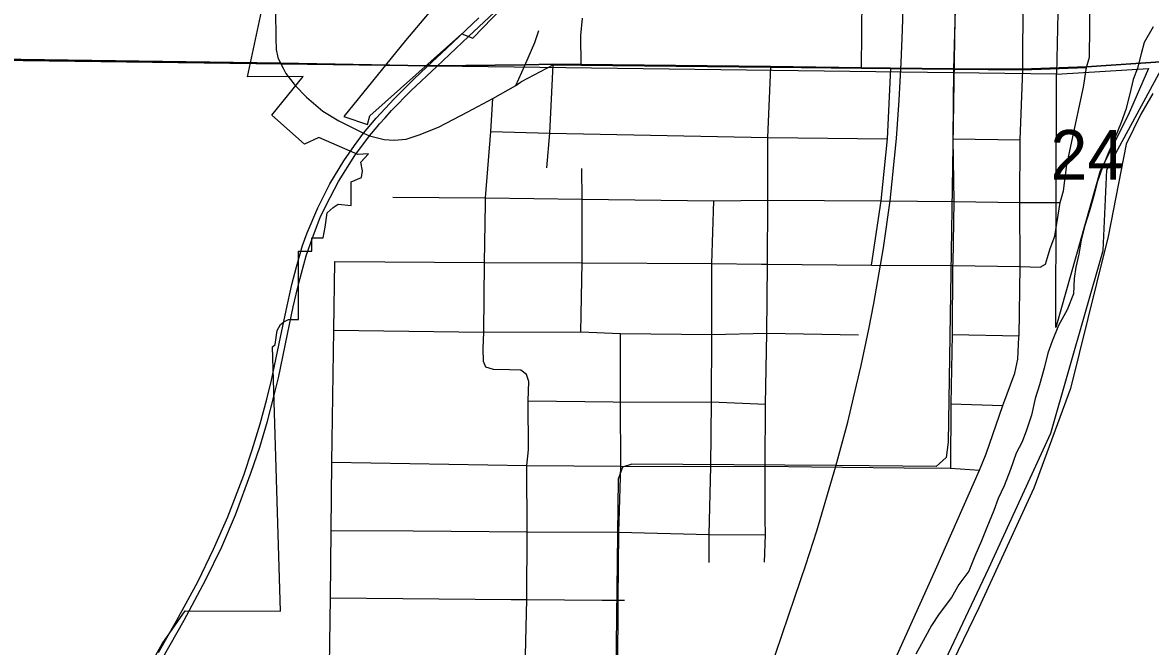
# Model space of a CAD drawing. Extents: x 0 to 34, y 0 to 22.
# Drawn here: x 7.567 to 8.519, y 18.613 to 19.139 of the extents above; entities that cross this region are included whole.
import ezdxf

# ---------------------------------------------------------------- set-up
doc = ezdxf.new("R2010")
doc.units = 0
for name, color, linetype in [('Default', 7, 'Continuous'), ('GM_X_City_Street', 7, 'Continuous'), ('GM_X_Corporation', 7, 'Continuous'), ('GM_X_County_Road', 7, 'Continuous'), ('GM_X_Major_River', 7, 'Continuous'), ('GM_X_Rail_Line', 7, 'Continuous'), ('GM_X_Section', 7, 'Continuous'), ('GM_X_Section_Text', 7, 'Continuous'), ('GM_X_State_Route', 7, 'Continuous'), ('SH_Cut_Line', 7, 'Continuous')]:
    doc.layers.add(name, color=color, linetype=linetype)

msp = doc.modelspace()

# ---------------------------------------------------------------- linework, layer by layer
at = {"layer": 'Default'}
for p, q in [((7.78452, 19.10445), (7.43931, 19.10971)), ((7.43931, 19.10971), (7.78452, 19.10445)), ((7.90755, 19.10221), (7.78452, 19.10445)), ((7.78452, 19.10445), (7.90755, 19.10221)), ((8.01461, 19.10384), (7.99063, 19.10309)), ((7.99063, 19.10309), (8.01461, 19.10384)), ((8.03819, 19.10356), (8.01461, 19.10384)), ((8.01461, 19.10384), (8.03819, 19.10356)), ((8.19825, 19.10168), (8.03819, 19.10356)), ((8.03819, 19.10356), (8.19825, 19.10168)), ((8.53181, 19.10605), (8.46497, 19.10144)), ((8.46497, 19.10144), (8.53181, 19.10605)), ((8.48217, 19.01472), (8.53181, 19.10605)), ((7.90825, 19.10222), (7.90755, 19.10221)), ((7.90755, 19.10221), (7.90825, 19.10222)), ((7.91626, 19.1023), (7.90825, 19.10222)), ((7.90825, 19.10222), (7.91626, 19.1023)), ((7.99063, 19.10309), (7.91626, 19.1023)), ((7.91626, 19.1023), (7.99063, 19.10309)), ((8.27493, 19.10078), (8.19825, 19.10168)), ((8.19825, 19.10168), (8.27493, 19.10078)), ((8.29966, 19.1005), (8.27493, 19.10078)), ((8.27493, 19.10078), (8.29966, 19.1005)), ((8.35257, 19.09993), (8.29966, 19.1005)), ((8.29966, 19.1005), (8.35257, 19.09993)), ((8.41097, 19.09961), (8.35257, 19.09993)), ((8.35257, 19.09993), (8.41097, 19.09961)), ((8.46497, 19.10144), (8.41097, 19.09961)), ((8.41097, 19.09961), (8.46497, 19.10144)), ((8.47905, 18.9465), (8.48217, 19.01472)), ((8.43501, 18.79263), (8.47905, 18.9465)), ((8.38262, 18.67861), (8.43501, 18.79263)), ((8.32753, 18.56228), (8.38262, 18.67861))]:
    msp.add_line(p, q, dxfattribs=at)
at = {"layer": 'GM_X_City_Street'}
for p, q in [((8.27513, 19.10024), (8.27561, 19.16337)), ((8.46748, 19.10967), (8.46826, 19.16076)), ((8.03812, 19.12792), (8.03943, 19.14251)), ((7.99919, 19.122), (8.00248, 19.13217)), ((8.03838, 19.10302), (8.03812, 19.12792)), ((7.99082, 19.10255), (7.99919, 19.122)), ((8.01179, 19.04554), (8.0148, 19.1033)), ((8.46516, 19.10089), (8.46748, 19.10967)), ((7.98324, 19.08564), (7.99082, 19.10255)), ((8.29698, 19.04065), (8.29986, 19.09996)), ((8.41116, 19.09907), (8.46516, 19.10089)), ((8.46253, 19.08438), (8.46516, 19.10089)), ((8.44845, 19.01895), (8.46253, 19.08438)), ((7.962, 19.04684), (7.96388, 19.07476)), ((7.95757, 18.99105), (7.962, 19.04684)), ((7.962, 19.04684), (8.01179, 19.04554)), ((8.00945, 19.01634), (8.01179, 19.04554)), ((8.01179, 19.04554), (8.19584, 19.04189)), ((8.19584, 19.04189), (8.29698, 19.04065)), ((8.29171, 18.98849), (8.29698, 19.04065)), ((8.35226, 19.04085), (8.40909, 19.0398)), ((8.44558, 18.99679), (8.44845, 19.01895)), ((8.03917, 18.99001), (8.03891, 19.01582)), ((7.87936, 18.99158), (7.95757, 18.99105)), ((7.9575, 18.9861), (7.95757, 18.99105)), ((7.95757, 18.99105), (8.03917, 18.99001)), ((8.03916, 18.93611), (8.03917, 18.99001)), ((8.03917, 18.99001), (8.15048, 18.98845)), ((8.15048, 18.98845), (8.19584, 18.98897)), ((8.19584, 18.98897), (8.29171, 18.98849)), ((8.44271, 18.98714), (8.44558, 18.99679)), ((7.95679, 18.93656), (7.9575, 18.9861)), ((8.14866, 18.93547), (8.15048, 18.98845)), ((8.28343, 18.93432), (8.29171, 18.98849)), ((8.29171, 18.98849), (8.35304, 18.98793)), ((8.35304, 18.98793), (8.40882, 18.98714)), ((8.40882, 18.98714), (8.44271, 18.98714)), ((8.43828, 18.95873), (8.44271, 18.98714)), ((8.43437, 18.9483), (8.43828, 18.95873)), ((8.43203, 18.94074), (8.43437, 18.9483)), ((7.82946, 18.87925), (7.83051, 18.93726)), ((7.83051, 18.93726), (7.95679, 18.93656)), ((7.95627, 18.87765), (7.95679, 18.93656)), ((7.95679, 18.93656), (8.03916, 18.93611)), ((8.03812, 18.87792), (8.03916, 18.93611)), ((8.03916, 18.93611), (8.14866, 18.93547)), ((8.14866, 18.87583), (8.14866, 18.93547)), ((8.14866, 18.93547), (8.19059, 18.93511)), ((8.19059, 18.93511), (8.19558, 18.93507)), ((8.19558, 18.93507), (8.28343, 18.93432)), ((8.28343, 18.93432), (8.352, 18.9339)), ((8.352, 18.9339), (8.40915, 18.93317)), ((8.40915, 18.93317), (8.42603, 18.9324)), ((8.42603, 18.9324), (8.43046, 18.93501)), ((8.43046, 18.93501), (8.43203, 18.94074)), ((7.82788, 18.76807), (7.82946, 18.87925)), ((7.82946, 18.87925), (7.95627, 18.87765)), ((7.95575, 18.86384), (7.95627, 18.87765)), ((7.95627, 18.87765), (8.03812, 18.87792)), ((8.03812, 18.87792), (8.07149, 18.87661)), ((8.07149, 18.87661), (8.14866, 18.87583)), ((8.07149, 18.81874), (8.07149, 18.87661)), ((8.1484, 18.819), (8.14866, 18.87583)), ((8.14866, 18.87583), (8.19506, 18.87687)), ((8.19506, 18.87687), (8.27248, 18.87557)), ((8.35147, 18.87583), (8.40804, 18.87453)), ((7.95601, 18.85289), (7.95575, 18.86384)), ((7.95783, 18.8482), (7.95601, 18.85289)), ((7.96435, 18.84611), (7.95783, 18.8482)), ((7.97791, 18.84585), (7.96435, 18.84611)), ((7.98755, 18.84559), (7.97791, 18.84585)), ((7.99224, 18.84194), (7.98755, 18.84559)), ((7.99407, 18.83621), (7.99224, 18.84194)), ((7.99355, 18.81978), (7.99407, 18.83621)), ((7.99355, 18.81978), (8.06534, 18.81882)), ((7.99381, 18.77833), (7.99355, 18.81978)), ((8.06534, 18.81882), (8.07149, 18.81874)), ((8.07149, 18.81874), (8.1484, 18.819)), ((8.07186, 18.76456), (8.07149, 18.81874)), ((8.14787, 18.76425), (8.1484, 18.819)), ((8.1484, 18.819), (8.19402, 18.81691)), ((8.35043, 18.81717), (8.39449, 18.81587)), ((7.9925, 18.7653), (7.99381, 18.77833)), ((7.82723, 18.71043), (7.82788, 18.76807)), ((7.82788, 18.76807), (7.9925, 18.7653)), ((7.99277, 18.70939), (7.9925, 18.7653)), ((7.9925, 18.7653), (8.07186, 18.76456)), ((8.14631, 18.7069), (8.14787, 18.76425)), ((8.19376, 18.7202), (8.19376, 18.76452)), ((8.33746, 18.67727), (8.37467, 18.76139)), ((8.19402, 18.70664), (8.19376, 18.7202)), ((7.82658, 18.6535), (7.82723, 18.71043)), ((7.82723, 18.71043), (7.89662, 18.70999)), ((7.89662, 18.70999), (7.99277, 18.70939)), ((7.99251, 18.65216), (7.99277, 18.70939)), ((7.99277, 18.70939), (8.07011, 18.70895)), ((8.07011, 18.70895), (8.14631, 18.7069)), ((8.14631, 18.68344), (8.14631, 18.7069)), ((8.14631, 18.7069), (8.19402, 18.70664)), ((8.19323, 18.6837), (8.19402, 18.70664)), ((8.28799, 18.56768), (8.33746, 18.67727)), ((7.82592, 18.59663), (7.82658, 18.6535)), ((7.82658, 18.6535), (7.97916, 18.65227)), ((7.97916, 18.65227), (7.99251, 18.65216)), ((7.99095, 18.5935), (7.99251, 18.65216)), ((7.99251, 18.65216), (8.05601, 18.65165)), ((8.05601, 18.65165), (8.06948, 18.65154)), ((8.06948, 18.65154), (8.07508, 18.6515))]:
    msp.add_line(p, q, dxfattribs=at)
at = {"layer": 'GM_X_Corporation'}
for p, q in [((7.75651, 19.09318), (7.7916, 19.25476)), ((7.94699, 19.12564), (7.99145, 19.17211)), ((7.9193, 19.15858), (7.89001, 19.12359)), ((7.89001, 19.12359), (7.83796, 19.0597)), ((7.85995, 19.06011), (7.93758, 19.1293)), ((7.93758, 19.1293), (7.94699, 19.12564)), ((7.80375, 19.09336), (7.75651, 19.09318)), ((7.77714, 19.06079), (7.80375, 19.09336)), ((8.521, 19.07889), (8.51095, 19.06147)), ((7.80485, 19.03639), (7.77714, 19.06079)), ((7.83796, 19.0597), (7.85805, 19.05291)), ((7.85805, 19.05291), (7.85995, 19.06011)), ((8.51095, 19.06147), (8.49851, 19.0364)), ((7.81687, 19.04199), (7.80485, 19.03639)), ((7.84992, 19.02753), (7.81687, 19.04199)), ((7.85868, 19.02822), (7.84992, 19.02753)), ((7.85241, 19.02103), (7.85868, 19.02822)), ((8.49851, 19.0364), (8.48326, 18.95844)), ((7.85385, 19.01373), (7.85241, 19.02103)), ((7.84407, 19.00448), (7.85284, 19.00801)), ((7.85284, 19.00801), (7.85385, 19.01373)), ((7.84406, 18.98462), (7.84407, 19.00448)), ((7.82386, 18.97824), (7.82891, 18.98295)), ((7.82891, 18.98295), (7.83329, 18.98564)), ((7.83329, 18.98564), (7.84406, 18.98462)), ((7.82217, 18.96613), (7.82386, 18.97824)), ((7.82049, 18.95723), (7.82217, 18.96613)), ((7.81102, 18.94588), (7.81102, 18.95724)), ((7.81102, 18.95724), (7.82049, 18.95723)), ((8.48326, 18.95844), (8.47357, 18.91863)), ((7.79962, 18.88848), (7.79965, 18.94589)), ((7.79965, 18.94589), (7.81102, 18.94588)), ((8.47357, 18.91863), (8.45146, 18.83021)), ((7.78437, 18.88417), (7.78732, 18.88645)), ((7.78732, 18.88645), (7.79122, 18.88849)), ((7.79122, 18.88849), (7.79962, 18.88848)), ((7.77996, 18.86729), (7.78174, 18.87903)), ((7.78174, 18.87903), (7.78437, 18.88417)), ((7.77778, 18.8652), (7.77996, 18.86729)), ((7.78438, 18.6423), (7.77778, 18.8652)), ((8.45146, 18.83021), (8.42049, 18.74604)), ((8.42049, 18.74604), (8.37415, 18.64504)), ((7.68445, 18.61475), (7.70398, 18.6427)), ((7.70398, 18.6427), (7.78438, 18.6423)), ((8.37415, 18.64504), (8.34608, 18.58755)), ((7.64793, 18.54939), (7.68445, 18.61475))]:
    msp.add_line(p, q, dxfattribs=at)
at = {"layer": 'GM_X_County_Road'}
for p, q in [((8.3546, 19.16285), (8.35277, 19.09939)), ((8.41116, 19.09907), (8.41169, 19.16233)), ((7.78025, 19.14883), (7.78044, 19.12569)), ((7.78044, 19.12569), (7.78083, 19.11616)), ((7.78083, 19.11616), (7.78219, 19.10936)), ((7.78219, 19.10936), (7.78471, 19.10391)), ((7.78471, 19.10391), (7.78662, 19.10028)), ((7.98803, 19.08903), (8.0148, 19.1033)), ((8.0148, 19.1033), (8.03531, 19.10306)), ((7.78662, 19.10028), (7.789, 19.09575)), ((7.789, 19.09575), (7.79686, 19.0857)), ((8.03531, 19.10306), (8.03838, 19.10302)), ((8.03838, 19.10302), (8.19844, 19.10114)), ((8.19584, 19.04189), (8.19844, 19.10114)), ((8.19844, 19.10114), (8.27513, 19.10024)), ((8.27513, 19.10024), (8.29986, 19.09996)), ((8.29986, 19.09996), (8.35277, 19.09939)), ((8.35277, 19.09939), (8.35226, 19.04085)), ((8.35277, 19.09939), (8.41116, 19.09907)), ((8.40909, 19.0398), (8.41116, 19.09907)), ((7.79686, 19.0857), (7.80645, 19.07604)), ((7.96388, 19.07476), (7.98324, 19.08564)), ((7.98324, 19.08564), (7.98713, 19.08855)), ((7.98713, 19.08855), (7.98803, 19.08903)), ((7.80645, 19.07604), (7.82035, 19.06408)), ((7.94261, 19.06347), (7.96388, 19.07476)), ((7.82035, 19.06408), (7.83369, 19.05595)), ((7.83369, 19.05595), (7.85471, 19.04542)), ((7.91791, 19.05064), (7.94261, 19.06347)), ((7.90154, 19.04417), (7.91791, 19.05064)), ((7.85471, 19.04542), (7.85969, 19.04327)), ((7.85969, 19.04327), (7.87202, 19.04033)), ((7.87202, 19.04033), (7.88058, 19.03955)), ((7.88058, 19.03955), (7.89069, 19.04053)), ((7.89069, 19.04053), (7.90154, 19.04417)), ((8.19584, 18.98897), (8.19584, 19.04189)), ((8.35226, 19.04085), (8.35304, 18.98793)), ((8.40882, 18.98714), (8.40909, 19.0398)), ((8.19558, 18.93507), (8.19584, 18.98897)), ((8.35304, 18.98793), (8.35204, 18.93594)), ((8.40915, 18.93317), (8.40882, 18.98714)), ((8.19506, 18.87687), (8.19558, 18.93507)), ((8.352, 18.9339), (8.35147, 18.87583)), ((8.35204, 18.93594), (8.352, 18.9339)), ((8.40804, 18.87453), (8.40915, 18.93317)), ((8.19402, 18.81691), (8.19506, 18.87687)), ((8.35147, 18.87583), (8.35043, 18.81717)), ((8.407, 18.85497), (8.40799, 18.87355)), ((8.40799, 18.87355), (8.40804, 18.87453)), ((8.40465, 18.84324), (8.407, 18.85497)), ((8.39449, 18.81587), (8.40465, 18.84324)), ((8.19376, 18.76452), (8.19402, 18.81691)), ((8.35043, 18.81717), (8.35017, 18.76295)), ((8.38041, 18.7752), (8.39449, 18.81587)), ((8.37467, 18.76139), (8.38041, 18.7752)), ((8.07011, 18.70895), (8.07186, 18.76456)), ((8.07186, 18.76456), (8.14787, 18.76425)), ((8.14787, 18.76425), (8.19376, 18.76452)), ((8.19376, 18.76452), (8.23286, 18.76412)), ((8.23286, 18.76412), (8.31107, 18.76334)), ((8.31107, 18.76334), (8.35017, 18.76295)), ((8.35017, 18.76295), (8.37467, 18.76139)), ((8.06948, 18.65154), (8.07011, 18.70895)), ((8.06944, 18.59273), (8.06948, 18.65154))]:
    msp.add_line(p, q, dxfattribs=at)
at = {"layer": 'GM_X_Major_River'}
for p, q in [((8.52143, 19.13512), (8.51372, 19.12208)), ((8.51372, 19.12208), (8.51125, 19.11255)), ((8.51125, 19.11255), (8.50808, 19.10035)), ((8.50808, 19.10035), (8.50447, 19.09079)), ((8.50447, 19.09079), (8.50167, 19.0786)), ((8.50167, 19.0786), (8.49813, 19.06563)), ((8.49813, 19.06563), (8.49418, 19.05456)), ((8.49418, 19.05456), (8.48876, 19.0408)), ((8.48876, 19.0408), (8.48294, 19.02778)), ((8.48294, 19.02778), (8.47824, 19.01594)), ((8.47824, 19.01594), (8.47393, 19.00409)), ((8.47393, 19.00409), (8.47147, 18.9938)), ((8.47147, 18.9938), (8.46756, 18.98007)), ((8.46756, 18.98007), (8.46327, 18.96671)), ((8.46327, 18.96671), (8.46046, 18.95527)), ((8.46046, 18.95527), (8.45841, 18.94347)), ((8.45841, 18.94347), (8.45597, 18.93243)), ((8.45597, 18.93243), (8.45464, 18.92291)), ((8.45464, 18.92291), (8.45413, 18.91)), ((8.45413, 18.91), (8.4487, 18.89662)), ((8.4487, 18.89662), (8.44138, 18.8832)), ((8.44138, 18.8832), (8.43595, 18.8702)), ((8.43595, 18.8702), (8.43235, 18.85989)), ((8.43235, 18.85989), (8.42919, 18.84731)), ((8.42919, 18.84731), (8.42529, 18.83319)), ((8.42529, 18.83319), (8.42172, 18.82174)), ((8.42172, 18.82174), (8.41858, 18.80764)), ((8.41858, 18.80764), (8.41427, 18.79504)), ((8.41427, 18.79504), (8.41067, 18.78511)), ((8.41067, 18.78511), (8.40555, 18.77553)), ((8.40555, 18.77553), (8.40089, 18.76178)), ((8.40089, 18.76178), (8.39547, 18.74801)), ((8.39547, 18.74801), (8.39037, 18.73729)), ((8.39037, 18.73729), (8.38677, 18.72736)), ((8.38677, 18.72736), (8.38098, 18.71283)), ((8.38098, 18.71283), (8.37627, 18.70174)), ((8.37627, 18.70174), (8.37083, 18.68873)), ((8.37083, 18.68873), (8.36577, 18.67611)), ((8.36577, 18.67611), (8.35727, 18.66495)), ((8.35727, 18.66495), (8.35104, 18.65383)), ((8.35104, 18.65383), (8.34069, 18.63997)), ((8.34069, 18.63997), (8.33405, 18.63036)), ((8.33405, 18.63036), (8.32894, 18.62039)), ((8.32894, 18.62039), (8.32087, 18.6062))]:
    msp.add_line(p, q, dxfattribs=at)
at = {"layer": 'GM_X_Rail_Line'}
for p, q in [((8.35732, 19.35599), (8.34834, 18.78484)), ((8.30959, 19.13274), (8.31068, 19.16341)), ((8.3086, 19.10474), (8.30959, 19.13274)), ((8.30692, 19.07337), (8.3086, 19.10474)), ((8.30455, 19.04102), (8.30692, 19.07337)), ((8.2992, 18.98848), (8.30455, 19.04102)), ((8.29356, 18.9487), (8.2992, 18.98848)), ((8.2901, 18.92763), (8.29356, 18.9487)), ((8.28555, 18.902), (8.2901, 18.92763)), ((8.2812, 18.88013), (8.28555, 18.902)), ((8.27476, 18.84956), (8.2812, 18.88013)), ((8.26833, 18.82225), (8.27476, 18.84956)), ((8.26339, 18.80177), (8.26833, 18.82225)), ((8.25349, 18.76454), (8.26339, 18.80177)), ((8.34834, 18.78484), (8.34661, 18.77195)), ((8.34661, 18.77195), (8.33813, 18.76448)), ((8.07319, 18.76378), (8.0696, 18.75357)), ((8.08121, 18.76631), (8.07319, 18.76378)), ((8.2533, 18.76509), (8.08121, 18.76631)), ((8.23736, 18.71025), (8.25349, 18.76454)), ((8.33813, 18.76448), (8.2533, 18.76509)), ((8.0696, 18.75357), (8.06613, 18.44879)), ((8.22806, 18.68155), (8.23736, 18.71025)), ((8.21876, 18.65404), (8.22806, 18.68155)), ((8.18383, 18.55104), (8.21876, 18.65404))]:
    msp.add_line(p, q, dxfattribs=at)
at = {"layer": 'GM_X_Section'}
for p, q in [((8.46027, 20.09858), (8.43983, 19.09537)), ((8.43983, 19.09537), (7.45846, 19.10807)), ((8.4391, 18.88156), (8.43983, 19.09537)), ((8.43983, 19.09537), (8.51743, 19.10007)), ((8.51743, 19.10007), (8.50016, 19.06073)), ((8.50016, 19.06073), (8.47661, 19.01363)), ((8.47661, 19.01363), (8.4391, 18.88156))]:
    msp.add_line(p, q, dxfattribs=at)
at = {"layer": 'GM_X_State_Route'}
for p, q in [((7.9432, 19.12716), (8.00836, 19.1887)), ((7.92468, 19.11701), (7.95203, 19.1428)), ((7.91646, 19.10176), (7.9432, 19.12716)), ((7.90845, 19.10167), (7.92468, 19.11701)), ((7.89496, 19.08144), (7.91646, 19.10176)), ((7.89717, 19.09101), (7.90845, 19.10167)), ((7.88041, 19.07436), (7.89717, 19.09101)), ((7.87835, 19.0646), (7.89496, 19.08144)), ((7.86532, 19.05833), (7.88041, 19.07436)), ((7.85471, 19.04542), (7.86532, 19.05833)), ((7.8682, 19.05335), (7.87294, 19.0586)), ((7.87294, 19.0586), (7.87835, 19.0646)), ((7.85969, 19.04327), (7.86624, 19.05102)), ((7.86624, 19.05102), (7.8682, 19.05335)), ((7.84684, 19.03526), (7.85471, 19.04542)), ((7.84715, 19.02661), (7.85969, 19.04327)), ((7.83785, 19.02217), (7.84684, 19.03526)), ((7.82626, 19.0028), (7.83785, 19.02217)), ((7.83355, 19.0049), (7.84715, 19.02661)), ((7.81592, 18.98244), (7.82626, 19.0028)), ((7.82302, 18.98494), (7.83355, 19.0049)), ((7.80705, 18.96161), (7.81592, 18.98244)), ((7.81806, 18.97449), (7.82302, 18.98494)), ((7.81138, 18.95733), (7.81806, 18.97449)), ((7.80313, 18.9508), (7.80705, 18.96161)), ((7.80603, 18.94211), (7.81138, 18.95733)), ((7.79791, 18.93274), (7.80313, 18.9508)), ((7.80021, 18.92024), (7.80603, 18.94211)), ((7.79395, 18.91776), (7.79791, 18.93274)), ((7.78914, 18.8961), (7.79395, 18.91776)), ((7.7977, 18.90966), (7.80021, 18.92024)), ((7.79519, 18.89908), (7.7977, 18.90966)), ((7.7845, 18.87344), (7.78914, 18.8961)), ((7.79039, 18.87587), (7.79519, 18.89908)), ((7.78282, 18.83917), (7.79039, 18.87587)), ((7.77698, 18.8371), (7.7845, 18.87344)), ((7.77306, 18.82129), (7.77698, 18.8371)), ((7.77899, 18.82346), (7.78282, 18.83917)), ((7.76743, 18.8004), (7.77306, 18.82129)), ((7.7735, 18.80275), (7.77899, 18.82346)), ((7.76064, 18.77843), (7.76743, 18.8004)), ((7.76697, 18.78065), (7.7735, 18.80275)), ((7.75986, 18.75969), (7.76697, 18.78065)), ((7.75349, 18.75713), (7.76064, 18.77843)), ((7.74002, 18.72194), (7.75349, 18.75713)), ((7.7464, 18.72359), (7.75986, 18.75969)), ((7.73485, 18.69674), (7.7464, 18.72359)), ((7.72806, 18.69469), (7.74002, 18.72194)), ((7.71475, 18.66723), (7.72806, 18.69469)), ((7.72124, 18.66854), (7.73485, 18.69674)), ((7.69674, 18.63424), (7.71475, 18.66723)), ((7.70305, 18.63467), (7.72124, 18.66854)), ((7.67745, 18.58945), (7.70305, 18.63467)), ((7.6815, 18.60746), (7.69674, 18.63424))]:
    msp.add_line(p, q, dxfattribs=at)
at = {"layer": 'SH_Cut_Line'}
for p, q in [((8.48217, 19.01472), (8.53181, 19.10605)), ((8.47905, 18.9465), (8.48217, 19.01472)), ((8.43501, 18.79263), (8.47905, 18.9465)), ((8.38262, 18.67861), (8.43501, 18.79263)), ((8.32753, 18.56228), (8.38262, 18.67861))]:
    msp.add_line(p, q, dxfattribs=at)

# ---------------------------------------------------------------- texts
at = {"layer": 'GM_X_Section_Text'}
msp.add_text('24', height=0.041856, rotation=0.00001, dxfattribs=at).set_placement((8.43463, 19.00637))

doc.saveas('drawing.dxf')
